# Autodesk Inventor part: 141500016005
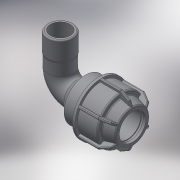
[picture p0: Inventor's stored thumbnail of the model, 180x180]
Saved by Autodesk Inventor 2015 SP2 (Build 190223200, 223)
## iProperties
Created: 2017-08
Part Number: 141500016005
Material: Generic
Description: L.14 90° ELBOW FEMALE ADAPTOR (SILVER) 16-1/2"
Document SubType Name: Modeling
Designer: KIM
Density: 1 g/cm^3
Appearance: Default
Author: KIM
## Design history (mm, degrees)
derived "141500.ipt"
feature "Solid1::141500.ipt"
feature "Solid2::141500.ipt"
tag "TaggingFeature1"
body "Solid1"
body "Solid2"
other parameters: "d1" = 16, "d4" = 15 deg, "d5" = 33, "d6" = 10.89, "d10" = 39, "d16" = 16.32, "d17" = 2.5, "d22" = 25.6, "d24" = 2.5, "d25" = 35.1, "d26" = 29.25, "d27" = 2.5, "d28" = 135 deg, "d29" = 1.5, "d31" = 0.8, "d46" = 150 deg, "d49" = 1.95, "d50" = 0, "d58" = 0.48, "d61" = 360 deg, "d63" = 14.4, "d94" = 39, "d95" = 18.631, "d96" = 24.2203, "d97" = 19, "d98" = 14.9048, "d99" = 21.79827, "d100" = 135 deg, "d108" = 0.8, "d112" = 24.7, "d113" = 66, "d114" = 51, "d115" = 21.79827, "d116" = 45 deg, "d117" = 0, "d118" = 0, "d_" = 16, "G_" = 18.631, "E_" = 39, "A_" = 66, "l_2" = 19, "A_1" = 39
